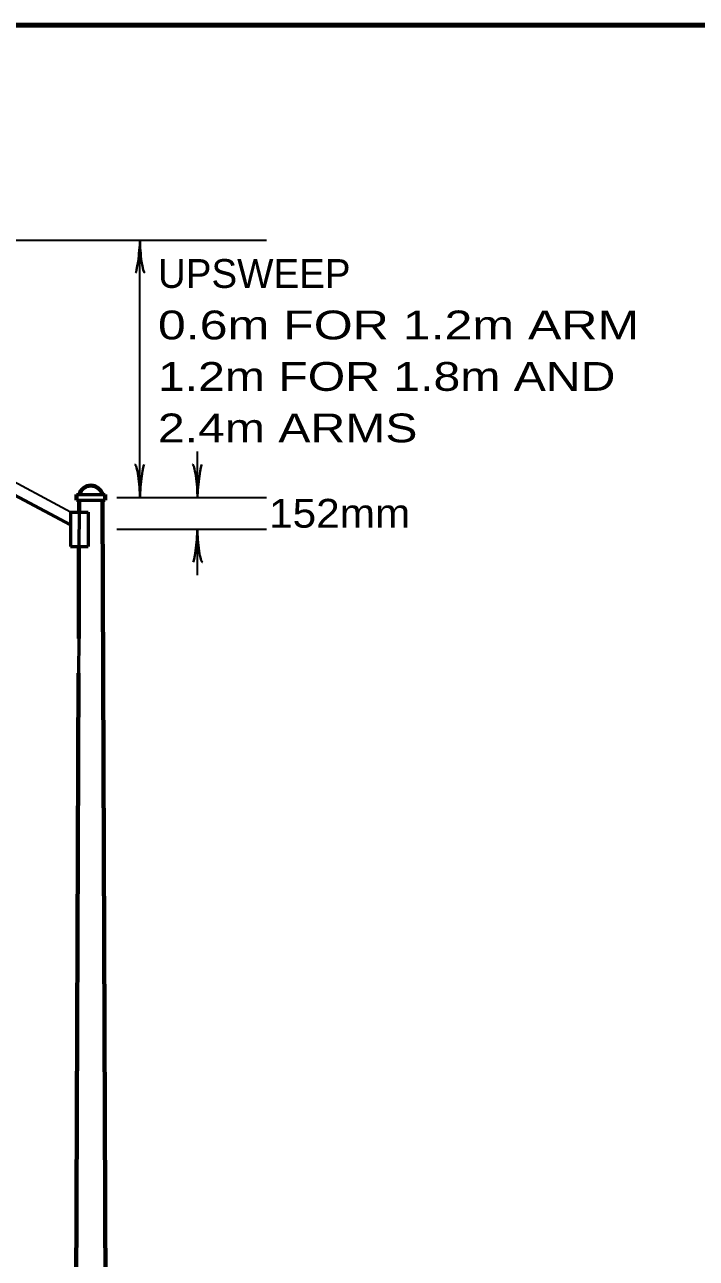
# Model space of a CAD drawing. Extents: x -20 to 693, y -19 to 435.
# Drawn here: x 283.2 to 342.4, y 320.5 to 429.4 of the extents above; entities that cross this region are included whole.
import ezdxf

# ---------------------------------------------------------------- set-up
doc = ezdxf.new("R2010")
doc.units = 0
doc.layers.add('1', color=7, linetype='Continuous', lineweight=53)

msp = doc.modelspace()

# ---------------------------------------------------------------- linework, layer by layer
at = {"layer": '1', "lineweight": 35}
for p, q in [((238.074, 410.341), (304.517, 410.341)), ((293.357, 387.649), (293.357, 410.341)), ((287.237, 386.369), (256.653, 402.65)), ((298.437, 387.649), (298.437, 391.709)), ((291.317, 387.649), (304.517, 387.649)), ((291.317, 384.869), (304.517, 384.869)), ((298.437, 380.789), (298.437, 384.869))]:
    msp.add_line(p, q, dxfattribs=at)
at = {"layer": '1'}
for p, q in [((287.237, 385.229), (256.194, 401.732)), ((287.757, 387.909), (290.297, 387.909)), ((287.757, 387.409), (290.297, 387.409)), ((287.237, 386.369), (288.777, 386.369)), ((287.237, 386.369), (287.237, 383.329)), ((287.997, 386.369), (287.977, 383.329)), ((288.777, 386.369), (288.777, 383.329)), ((287.237, 383.329), (288.777, 383.329)), ((287.957, 375.209), (287.937, 372.149))]:
    msp.add_line(p, q, dxfattribs=at)
at = {"layer": '1', "lineweight": 70}
for p, q in [((287.757, 387.909), (287.757, 387.409)), ((287.997, 387.409), (287.997, 386.369)), ((290.037, 387.409), (290.537, 261.409)), ((290.297, 387.909), (290.297, 387.409)), ((287.977, 383.329), (287.957, 375.209)), ((287.937, 372.149), (287.497, 261.409))]:
    msp.add_line(p, q, dxfattribs=at)
at = {"layer": '1', "lineweight": 158}
msp.add_lwpolyline([(687.723, 429.353), (27.973, 429.27), (28.056, -9.063)], dxfattribs=at)
at = {"layer": '1', "lineweight": 70}
msp.add_arc((289.025, 387.654), 1.044, 13.87704, 166.12296, dxfattribs=at)
at = {"layer": '1', "lineweight": 40}
for centre, major_axis, ratio, start_param, end_param in [((293.145, 409.221), (0.176, 1.756), 0.07063, 3.1407148, 5.41811), ((293.633, 409.25), (-0.156, 1.786), 0.122415, 0.8963533, 3.1415927), ((293.066, 388.75), (0.159, -1.814), 0.122415, 0.8963533, 3.1415927), ((293.066, 388.75), (0.159, -1.814), 0.122415, 0.8963533, 3.1415927), ((293.562, 388.78), (0.178, 1.785), 0.07063, 6.2823074, 8.5597026), ((293.562, 388.78), (0.178, 1.785), 0.07063, 6.2823074, 8.5597026), ((298.147, 388.75), (0.159, -1.814), 0.122415, 0.8963533, 3.1415927), ((298.147, 388.75), (0.159, -1.814), 0.122415, 0.8963533, 3.1415927), ((298.642, 388.78), (0.178, 1.785), 0.07063, 6.2823074, 8.5597026), ((298.642, 388.78), (0.178, 1.785), 0.07063, 6.2823074, 8.5597026), ((298.212, 383.721), (-0.178, -1.785), 0.07063, 6.2823074, 8.5597026), ((298.212, 383.721), (-0.178, -1.785), 0.07063, 6.2823074, 8.5597026), ((298.708, 383.751), (-0.159, 1.814), 0.122415, 0.8963533, 3.1415927), ((298.708, 383.751), (-0.159, 1.814), 0.122415, 0.8963533, 3.1415927)]:
    msp.add_ellipse(centre, major_axis=major_axis, ratio=ratio, start_param=start_param, end_param=end_param, dxfattribs=at)

# ---------------------------------------------------------------- texts
at = {"layer": '1'}
msp.add_text('UPSWEEP', height=2.54, dxfattribs=at).set_placement((294.941, 406.137))
for s, width, p in [('0.6m FOR 1.2m ARM', 1.3, (294.941, 401.597)), ('1.2m FOR 1.8m AND', 1.25, (294.941, 397.057)), ('2.4m ARMS', 1.25, (294.941, 392.517)), ('152mm', 1.1, (304.737, 384.989))]:
    msp.add_text(s, height=2.54, dxfattribs=dict(at, width=width)).set_placement(p)

doc.saveas('drawing.dxf')
